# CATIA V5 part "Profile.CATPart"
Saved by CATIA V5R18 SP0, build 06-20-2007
Part number: Profile
Bounding box of the stored display mesh (mm): x -58.221 to 95.108, y -67.694 to 79.25, z 0 to 0
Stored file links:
  D:\Shriniwas\v5_r19\c16_CAT_v5r19\c16_Part\Point Curve\Profile.CATPart
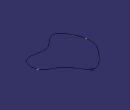
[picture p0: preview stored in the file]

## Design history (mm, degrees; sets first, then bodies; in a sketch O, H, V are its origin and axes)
Body1 (main body)
  Sketch1 on xy-plane, origin (0, 0, 0), H (1, 0, 0), V (0, 1, 0)
    spline S1 through (-56.936, -9.8228) (-36.2121, 48.255) (9.4222, 78.5932) (39.7622, 40.0274) (63.9393, 19.9693) (91.4937, -1.8468) (86.3206, -40.9294) (25.4678, -42.273) (-9.6787, -66.1719) (-56.936, -9.8228)
    point P1 (-56.936, -9.8228)
    point P2 (-56.936, -9.8228)
    coincidence: P1 P2
  Sketch2 on yz-plane, origin (0, 0, 0), H (0, 1, 0), V (0, 0, 1)
    line L1 (0, 84.1472) -> (0, 110.8669)
    point P1 (0, 84.1472)
    line L2 (0, 110.8669) -> (-22.6823, 110.8669)
    coincidence: P1 V
    vertical: L1 V
    horizontal: L2 H
  Point1: type OnCurve, Support Sketch1, Length 0, RefPoint {extremum Reference Sketch1, Direction (1, 2, 3)}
